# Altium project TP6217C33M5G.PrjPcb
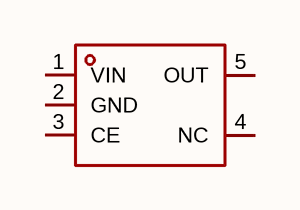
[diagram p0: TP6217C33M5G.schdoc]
1 sheet, 1 parts. Net scope: global (net labels, ports and power ports of the same name join across sheets).

## Sheet TP6217C33M5G.schdoc
size 127 x 101 mm

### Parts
U?  tp6217c33m5g  [SOT-23-5_L2.9-W1.6-P0.95-LS2.8-BR]  (value not drawn)

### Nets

Not connected (* = marked no-connect by the designer): U? 1(VIN) 2(GND) 3(CE) 4(NC) 5(OUT)

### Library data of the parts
U? = tp6217c33m5g: 输出极性:正极;工作电压:5.5V;输出电压:3.3V;输出电流:800mA;电源纹波抑制比(PSRR):70dB@(1kHz);输出类型:固定;; Manufacturer: TECH PUBLIC(台舟); AddInBom: yes; ModelId: 7ba65df16e7b4570af156e925f9c37fe; ModelTransform: 114.173,114.173,0,90,0,0,0,0,0; Output Configuration: 正极; Voltage - Supply: 5.5V; Output Voltage: 3.3V; Output Current: 800mA; Voltage Dropout: 400mV@(800mA); standby current: 25uA; Output Type: 固定; Number of Outputs: 1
